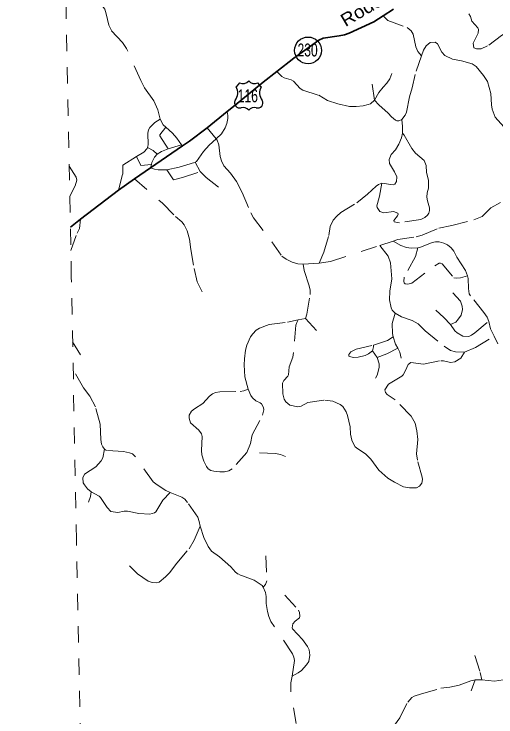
# Model space of a CAD drawing. Extents: x 220.8 to 246.7, y 7287.6 to 7315.8.
# Drawn here: x 220.754 to 223.739, y 7294.66 to 7299.009 of the extents above; entities that cross this region are included whole.
import ezdxf
from ezdxf.enums import TextEntityAlignment as Align

# ---------------------------------------------------------------- set-up
doc = ezdxf.new("R2010")
doc.units = 0
doc.header["$LTSCALE"] = 0.032
for name, pattern in [('DOTTED', [1.5, 0.3, -1.2]), ('MEDIUM_DASHED', [4.5, 3, -1.5]), ('SHORT_DASHED', [2.7, 1.5, -1.2])]:
    doc.linetypes.add(name, pattern=pattern)
for name, color, linetype, lineweight in [('12', 7, 'Continuous', 25), ('13', 7, 'Continuous', 25), ('2', 7, 'Continuous', 35), ('35', 7, 'SHORT_DASHED', 13), ('6', 7, 'MEDIUM_DASHED', 13), ('7', 7, 'DOTTED', 13)]:
    doc.layers.add(name, color=color, linetype=linetype, lineweight=lineweight)
doc.layers.add('61', color=7, linetype='Continuous')

msp = doc.modelspace()

# ---------------------------------------------------------------- linework, layer by layer
at = {"layer": '12'}
for p, q in [((222.1503, 7298.5835), (222.1294, 7298.5592)), ((222.2856, 7298.5594), (222.2646, 7298.5835))]:
    msp.add_line(p, q, dxfattribs=at)
for centre, radius, start, end in [((222.1711, 7298.6236), 0.0452, 242.5287, 323.4161), ((222.2437, 7298.6236), 0.0452, 216.5968, 297.4912), ((222.0662, 7298.521), 0.0738, 320.9608, 31.1419), ((222.3486, 7298.521), 0.0738, 148.687, 219.0536), ((222.1514, 7298.4594), 0.0316, 151.5003, 286.5066), ((222.2635, 7298.4594), 0.0316, 253.4942, 28.4996), ((222.1734, 7298.3877), 0.0433, 38.3472, 107.6219), ((222.2414, 7298.3877), 0.0433, 72.467, 141.6528)]:
    msp.add_arc(centre, radius, start, end, dxfattribs=at)
at = {"layer": '13'}
msp.add_circle((222.5751, 7298.7839), 0.083, dxfattribs=at)
at = {"layer": '2'}
msp.add_lwpolyline([(221.1029, 7297.6911), (221.1659, 7297.7392), (221.4019, 7297.9193), (221.5013, 7297.9903), (221.6003, 7298.0579), (221.7976, 7298.1926), (221.8414, 7298.2225), (221.95, 7298.3053), (222.0739, 7298.4051), (222.1143, 7298.4377), (222.298, 7298.5873), (222.3818, 7298.653), (222.4869, 7298.7356), (222.6418, 7298.8484), (222.6693, 7298.8602), (222.7677, 7298.8733), (222.8005, 7298.8799), (222.8307, 7298.8904), (222.9829, 7298.9612), (223.0409, 7298.998), (223.1049, 7299.0386)], dxfattribs=at)
at = {"layer": '35'}
msp.add_lwpolyline([(221.3035, 7287.6034), (221.271, 7289.2329), (221.2386, 7290.8624), (221.2062, 7292.4919), (221.1738, 7294.1214), (221.1414, 7295.7509), (221.109, 7297.3804), (221.0767, 7299.0099), (221.0443, 7300.6394), (221.0121, 7302.2689), (220.9798, 7303.8984), (220.9475, 7305.5279), (220.9153, 7307.1574), (220.883, 7308.7869), (220.8508, 7310.4164), (220.8187, 7312.0459), (220.7865, 7313.6754), (220.7543, 7315.3049)], dxfattribs=at)
at = {"layer": '6'}
for p, q in [((221.95, 7298.3053), (222.0063, 7298.2361)), ((221.7919, 7298.2006), (221.7093, 7298.1757)), ((221.7919, 7298.2006), (221.7976, 7298.1926)), ((221.9077, 7298.0339), (221.8767, 7298.093))]:
    msp.add_line(p, q, dxfattribs=at)
for points in [[(221.6588, 7298.3593), (221.6455, 7298.4161), (221.6203, 7298.4715), (221.562, 7298.5515), (221.5389, 7298.5971), (221.4513, 7298.7962), (221.426, 7298.8327), (221.358, 7298.9063), (221.3412, 7298.94), (221.3257, 7299.0101), (221.3159, 7299.0402), (221.2539, 7299.1225)], [(222.0063, 7298.2361), (222.0399, 7298.2688), (222.062, 7298.3042), (222.0724, 7298.3323), (222.079, 7298.3618), (222.079, 7298.381), (222.0739, 7298.4051)], [(221.58, 7298.1827), (221.5845, 7298.1988), (221.5838, 7298.2717), (221.5866, 7298.292), (221.595, 7298.3074), (221.6259, 7298.339), (221.6588, 7298.3593)], [(221.6588, 7298.3593), (221.6778, 7298.3243), (221.6935, 7298.3085)], [(221.6935, 7298.3085), (221.6567, 7298.2619), (221.6581, 7298.2549), (221.7093, 7298.1757)], [(221.6935, 7298.3085), (221.736, 7298.2724), (221.7633, 7298.2408), (221.7919, 7298.2006)], [(221.8767, 7298.093), (221.8841, 7298.0967), (221.9276, 7298.158), (221.9631, 7298.1986), (222.0063, 7298.2361)], [(222.0063, 7298.2361), (222.0126, 7298.2289), (222.0227, 7298.2006), (222.0318, 7298.1274), (222.0382, 7298.1009), (222.0537, 7298.0707), (222.094, 7298.025), (222.1314, 7297.9729), (222.168, 7297.9044), (222.221, 7297.7791), (222.2366, 7297.749), (222.3508, 7297.599), (222.413, 7297.5113), (222.4395, 7297.4921), (222.4761, 7297.4729), (222.5117, 7297.4628), (222.5453, 7297.4621), (222.6438, 7297.4675), (222.7138, 7297.4784), (223.0201, 7297.5772), (223.1024, 7297.6042)], [(221.5122, 7298.127), (221.5571, 7298.1553), (221.5782, 7298.1763), (221.58, 7298.1827)], [(221.58, 7298.1827), (221.6153, 7298.1644), (221.6416, 7298.1414)], [(221.6416, 7298.1414), (221.6231, 7298.123), (221.6076, 7298.0908), (221.6049, 7298.0787)], [(221.7093, 7298.1757), (221.6672, 7298.1581), (221.6416, 7298.1414)], [(221.4019, 7297.9193), (221.4274, 7298.0192), (221.4281, 7298.0739), (221.5122, 7298.127)], [(221.5122, 7298.127), (221.5389, 7298.0718), (221.6049, 7298.0787)], [(221.7015, 7298.0455), (221.7762, 7298.0613), (221.8767, 7298.093)], [(221.0954, 7298.0676), (221.1392, 7297.9996), (221.1427, 7297.9807), (221.1336, 7297.947), (221.0991, 7297.8825)], [(221.6049, 7298.0787), (221.6003, 7298.0579), (221.6234, 7298.0487), (221.647, 7298.045), (221.7015, 7298.0455)], [(221.7015, 7298.0455), (221.7423, 7297.9837), (221.7969, 7297.9977), (221.9077, 7298.0339)], [(221.9077, 7298.0339), (221.9431, 7297.997), (222.0207, 7297.9387)], [(223.1024, 7297.6042), (223.1306, 7297.6137), (223.2449, 7297.631), (223.2824, 7297.6411), (223.3848, 7297.6841), (223.4652, 7297.7005), (223.6024, 7297.7352), (223.6526, 7297.7563), (223.7066, 7297.8102), (223.7678, 7297.8431)], [(221.1057, 7297.5453), (221.1446, 7297.6527), (221.1603, 7297.6822), (221.1659, 7297.7392)], [(223.7503, 7296.9678), (223.7272, 7297.0158), (223.7047, 7297.0602), (223.6937, 7297.1074), (223.6834, 7297.134), (223.6647, 7297.1623), (223.5806, 7297.2658), (223.5737, 7297.2782), (223.5682, 7297.3106), (223.5668, 7297.3734), (223.5622, 7297.3891), (223.5495, 7297.4217), (223.4971, 7297.5045), (223.4785, 7297.541), (223.4606, 7297.5617), (223.4385, 7297.5803), (223.415, 7297.5921), (223.3867, 7297.599), (223.3647, 7297.599), (223.3433, 7297.5955), (223.2681, 7297.5645), (223.2552, 7297.5626), (223.2129, 7297.5603), (223.1846, 7297.5638), (223.1488, 7297.5762), (223.1024, 7297.6042)], [(222.3237, 7295.3115), (222.3155, 7295.3612), (222.3155, 7295.4042), (222.3114, 7295.4294), (222.2975, 7295.4626), (222.2909, 7295.4737), (222.2405, 7295.5057), (222.1423, 7295.5439), (222.1253, 7295.5548), (222.0967, 7295.5882), (222.0265, 7295.6496), (221.9774, 7295.685), (221.9556, 7295.7136), (221.929, 7295.7702), (221.9073, 7295.8395), (221.901, 7295.8697), (221.8915, 7295.8963), (221.8295, 7295.9863), (221.8111, 7296.0067), (221.7927, 7296.019), (221.722, 7296.0485), (221.6952, 7296.0613), (221.64, 7296.0953), (221.6154, 7296.1144), (221.5057, 7296.2685), (221.4873, 7296.2869), (221.4696, 7296.2944), (221.4321, 7296.3019), (221.3264, 7296.308), (221.3148, 7296.3162), (221.3039, 7296.3305), (221.2964, 7296.3476), (221.2923, 7296.3769), (221.2876, 7296.4716), (221.2583, 7296.5786), (221.2242, 7296.6454), (221.1853, 7296.6966), (221.1204, 7296.8097)], [(222.5022, 7294.6182), (222.4675, 7294.8152), (222.4688, 7294.8711), (222.4773, 7294.9129), (222.492, 7295.0095), (222.4879, 7295.0293), (222.4791, 7295.0511), (222.3455, 7295.2501), (222.3318, 7295.2815), (222.3237, 7295.3115)]]:
    msp.add_lwpolyline(points, dxfattribs=at)
at = {"layer": '7'}
for p, q in [((222.9864, 7298.4753), (222.9673, 7298.6085)), ((222.5136, 7297.1159), (222.5599, 7297.1246)), ((222.5599, 7297.1246), (222.6296, 7297.0471)), ((221.1169, 7296.9816), (221.1657, 7296.9012)), ((223.0031, 7296.8848), (222.9732, 7296.9251)), ((223.61, 7294.8891), (223.5844, 7294.8218)), ((223.61, 7294.8891), (223.6514, 7294.8899))]:
    msp.add_line(p, q, dxfattribs=at)
for points in [[(223.9969, 7298.9547), (223.9678, 7298.9474), (223.8873, 7298.9067), (223.7978, 7298.89), (223.7734, 7298.8767), (223.6873, 7298.8116), (223.6479, 7298.7928), (223.6183, 7298.7928), (223.6012, 7298.8009), (223.5982, 7298.8288), (223.6286, 7298.8904), (223.6303, 7298.9127), (223.6264, 7298.9243), (223.5892, 7298.9654), (223.581, 7298.9945), (223.5703, 7299.0104)], [(223.0409, 7298.998), (223.0698, 7298.9692), (223.1886, 7298.9255), (223.2136, 7298.9042), (223.2261, 7298.8848), (223.243, 7298.8054), (223.2555, 7298.7767), (223.2767, 7298.751)], [(223.2767, 7298.751), (223.2907, 7298.7864), (223.3065, 7298.8121), (223.3313, 7298.8332), (223.3615, 7298.8344), (223.376, 7298.8249), (223.4046, 7298.7731), (223.4228, 7298.7528), (223.4696, 7298.7309), (223.5259, 7298.7201), (223.5905, 7298.7002), (223.6158, 7298.6849), (223.6618, 7298.6286), (223.6854, 7298.5913), (223.7065, 7298.5164), (223.7102, 7298.4464), (223.7144, 7298.4203), (223.7342, 7298.371), (223.7873, 7298.3118), (223.8274, 7298.2563), (223.8386, 7298.2348)], [(223.2767, 7298.751), (223.2386, 7298.6354), (223.2205, 7298.5535), (223.2042, 7298.4978), (223.1848, 7298.4009), (223.1767, 7298.3834), (223.1555, 7298.3559)], [(222.3818, 7298.653), (222.4126, 7298.6226), (222.427, 7298.6148), (222.4699, 7298.6029), (222.4846, 7298.5945), (222.5261, 7298.5491), (222.5426, 7298.5375), (222.6414, 7298.5069), (222.6962, 7298.475), (222.7605, 7298.4525), (222.8322, 7298.4366), (222.8737, 7298.4363), (222.9173, 7298.4409), (222.9479, 7298.4493), (222.9619, 7298.4542), (222.9864, 7298.4753)], [(222.9864, 7298.4753), (223.0137, 7298.5235), (223.0398, 7298.5576), (223.0628, 7298.5806), (223.0821, 7298.6087), (223.094, 7298.6422)], [(223.1555, 7298.3559), (223.1367, 7298.349), (223.1254, 7298.349), (223.1173, 7298.3528), (223.0911, 7298.3728), (223.0717, 7298.3953), (223.0129, 7298.4466), (222.9864, 7298.4753)], [(223.1593, 7298.2723), (223.1598, 7298.3124), (223.1555, 7298.3559)], [(223.1593, 7298.2723), (223.1702, 7298.2593), (223.2187, 7298.1769), (223.2411, 7298.1488), (223.2932, 7298.1019), (223.3068, 7298.0722), (223.3094, 7298.0279), (223.3219, 7297.9804), (223.3203, 7297.9314), (223.3135, 7297.9028), (223.3115, 7297.8767), (223.3141, 7297.8538), (223.3271, 7297.8105), (223.3281, 7297.7933), (223.3229, 7297.7772), (223.3151, 7297.7652), (223.2979, 7297.7511), (223.2729, 7297.7381), (223.1405, 7297.7172), (223.1087, 7297.724), (223.1056, 7297.7323), (223.1296, 7297.7605), (223.1332, 7297.7714), (223.1311, 7297.7766), (223.1051, 7297.7871), (223.0436, 7297.7798), (223.0206, 7297.7876), (223.0039, 7297.8126), (223.0019, 7297.823), (223.0045, 7297.8366), (223.017, 7297.8814), (223.0326, 7297.9617)], [(223.0326, 7297.9617), (223.1014, 7297.9528), (223.1118, 7297.9565), (223.1238, 7297.9731), (223.1243, 7298.0008), (223.1103, 7298.0336), (223.08, 7298.0852), (223.0769, 7298.1092), (223.0894, 7298.1399), (223.116, 7298.1696), (223.1374, 7298.203), (223.1535, 7298.2421), (223.1593, 7298.2723)], [(221.5013, 7297.9903), (221.673, 7297.8378), (221.7544, 7297.7572), (221.7931, 7297.7241), (221.8073, 7297.7052), (221.8262, 7297.6684), (221.8418, 7297.6169), (221.8492, 7297.5529), (221.869, 7297.4338), (221.8874, 7297.3528), (221.9187, 7297.2902)], [(222.6438, 7297.4675), (222.6735, 7297.5358), (222.7037, 7297.638), (222.7126, 7297.6938), (222.7308, 7297.7329), (222.7532, 7297.7589), (222.7777, 7297.7808), (222.8763, 7297.8418), (222.9435, 7297.8939), (222.9961, 7297.9434), (223.0112, 7297.9544), (223.0326, 7297.9617)], [(223.0201, 7297.5772), (223.0703, 7297.5114), (223.0858, 7297.4691), (223.0935, 7297.3709), (223.0806, 7297.295), (223.0785, 7297.2407), (223.0904, 7297.1917), (223.0966, 7297.1777), (223.1139, 7297.1583)], [(223.2552, 7297.5626), (223.2414, 7297.5093), (223.1711, 7297.3812), (223.1686, 7297.3541), (223.1702, 7297.3465), (223.1773, 7297.3407), (223.1928, 7297.3382), (223.2183, 7297.3444), (223.3602, 7297.452), (223.3861, 7297.4666), (223.3962, 7297.4674), (223.4058, 7297.4632), (223.4786, 7297.3762), (223.4961, 7297.3741), (223.52, 7297.3771), (223.5622, 7297.3891)], [(222.5599, 7297.1246), (222.5682, 7297.1513), (222.5881, 7297.2728), (222.5873, 7297.2995), (222.5813, 7297.3273), (222.5501, 7297.4225), (222.5453, 7297.4621)], [(223.4725, 7297.284), (223.5189, 7297.2329), (223.5299, 7297.2021), (223.5309, 7297.1801), (223.5231, 7297.1456), (223.5001, 7297.1139), (223.49, 7297.1033), (223.4581, 7297.0877)], [(223.1139, 7297.1583), (223.0966, 7297.0935), (223.0976, 7297.032), (223.1023, 7297.0116)], [(223.1139, 7297.1583), (223.1534, 7297.1359), (223.2201, 7297.1121), (223.2578, 7297.0914), (223.3007, 7297.0481), (223.4174, 7296.954), (223.4582, 7296.9267), (223.4877, 7296.9184), (223.5449, 7296.9171)], [(223.3654, 7297.1764), (223.4164, 7297.1314), (223.4581, 7297.0877)], [(222.2035, 7296.6882), (222.1827, 7296.7636), (222.1789, 7296.8377), (222.1808, 7296.8753), (222.1879, 7296.9298), (222.1958, 7296.9599), (222.2192, 7297.0107), (222.2323, 7297.0313), (222.2541, 7297.0524), (222.2737, 7297.0663), (222.3335, 7297.0874), (222.4471, 7297.1032), (222.5136, 7297.1159)], [(222.5136, 7297.1159), (222.505, 7297.1008), (222.5002, 7297.0842), (222.4847, 7296.9155), (222.4799, 7296.8855), (222.459, 7296.8255), (222.4536, 7296.7768), (222.4504, 7296.7693), (222.4242, 7296.7409), (222.4172, 7296.7259), (222.4199, 7296.6595), (222.4279, 7296.6269), (222.4376, 7296.6103), (222.4622, 7296.5899), (222.5109, 7296.5787), (222.5329, 7296.5824), (222.5736, 7296.6044), (222.678, 7296.6205), (222.7278, 7296.6146), (222.7744, 7296.5937), (222.7899, 7296.5808), (222.8113, 7296.5466), (222.8194, 7296.5257), (222.836, 7296.4545), (222.8381, 7296.41), (222.8467, 7296.3725), (222.8579, 7296.3452), (222.8676, 7296.3318), (222.8831, 7296.3179), (222.9307, 7296.2874), (222.9629, 7296.2542), (223.0132, 7296.1867), (223.07, 7296.1369), (223.1112, 7296.1118), (223.1669, 7296.0845), (223.2038, 7296.0775), (223.2477, 7296.0764), (223.2649, 7296.0877), (223.2788, 7296.1059), (223.2836, 7296.1284), (223.282, 7296.1428), (223.252, 7296.2483), (223.2472, 7296.2874), (223.2552, 7296.3763), (223.2493, 7296.4304), (223.2376, 7296.4775), (223.2135, 7296.5209), (223.1139, 7296.6221), (223.0641, 7296.6558), (223.0539, 7296.667), (223.0496, 7296.6831), (223.0732, 7296.7179), (223.1556, 7296.7688), (223.1642, 7296.7768), (223.1792, 7296.8025), (223.1953, 7296.8405), (223.2113, 7296.8539), (223.29, 7296.8432), (223.3966, 7296.8641), (223.4137, 7296.8636), (223.4576, 7296.8534), (223.4844, 7296.8571), (223.5203, 7296.8796), (223.5449, 7296.9171)], [(223.4581, 7297.0877), (223.4844, 7297.0486), (223.4978, 7297.0367), (223.5341, 7297.0165), (223.5704, 7297.0146), (223.5869, 7297.0211), (223.6076, 7297.0358), (223.6937, 7297.1074)], [(222.9805, 7296.9599), (223.0667, 7296.9887), (223.1023, 7297.0116)], [(223.1023, 7297.0116), (223.1173, 7296.967), (223.1309, 7296.941)], [(223.5449, 7296.9171), (223.6124, 7296.9449), (223.7272, 7297.0158)], [(222.9732, 7296.9251), (222.9504, 7296.9055), (222.9292, 7296.8962), (222.8853, 7296.8859), (222.8569, 7296.8848), (222.8326, 7296.891), (222.8285, 7296.8931), (222.828, 7296.9034), (222.8409, 7296.9194), (222.8735, 7296.9349), (222.9805, 7296.9599)], [(222.9732, 7296.9251), (222.9809, 7296.9494), (222.9805, 7296.9599)], [(223.0031, 7296.8848), (223.0625, 7296.906), (223.1309, 7296.941)], [(223.1309, 7296.941), (223.1431, 7296.9163), (223.1524, 7296.8797)], [(222.9938, 7296.7552), (223.0031, 7296.7753), (223.0155, 7296.8223), (223.0155, 7296.8445), (223.0031, 7296.8848)], [(222.1951, 7296.2968), (222.1042, 7296.194), (222.0848, 7296.1826), (222.0585, 7296.1756), (222.029, 7296.176), (221.9917, 7296.1804), (221.9724, 7296.1852), (221.9561, 7296.194), (221.9456, 7296.2085), (221.9293, 7296.2415), (221.9179, 7296.2814), (221.9144, 7296.3082), (221.9192, 7296.3948), (221.9153, 7296.4106), (221.8986, 7296.4334), (221.8476, 7296.4786), (221.8389, 7296.5076), (221.8393, 7296.5265), (221.8529, 7296.5516), (221.8709, 7296.5665), (221.9241, 7296.5994), (221.9654, 7296.6442), (221.9842, 7296.6587), (222.0018, 7296.6671), (222.0282, 7296.671), (222.1542, 7296.6732), (222.1775, 7296.6767), (222.2035, 7296.6882)], [(222.1951, 7296.2968), (222.2188, 7296.3518), (222.2289, 7296.4063), (222.2932, 7296.5263), (222.3015, 7296.5609), (222.2996, 7296.5748), (222.2861, 7296.597), (222.2793, 7296.6034), (222.2515, 7296.6161), (222.2301, 7296.6338), (222.2199, 7296.6496), (222.2035, 7296.6882)], [(221.3148, 7296.3162), (221.3034, 7296.264), (221.2929, 7296.2446), (221.2598, 7296.2078), (221.1899, 7296.1626), (221.1799, 7296.1385), (221.1831, 7296.1085), (221.1899, 7296.0949), (221.2083, 7296.0702), (221.2327, 7296.0527)], [(222.4358, 7296.2716), (222.4042, 7296.2829), (222.3741, 7296.2889), (222.1951, 7296.2968)], [(221.2146, 7295.9882), (221.2288, 7296.024), (221.2327, 7296.0527)], [(221.2327, 7296.0527), (221.2813, 7296.0261), (221.2902, 7296.0182), (221.3317, 7295.9551), (221.3538, 7295.931), (221.3964, 7295.9252), (221.4373, 7295.9336), (221.4573, 7295.9336), (221.5261, 7295.9178), (221.5949, 7295.9136), (221.6244, 7295.922), (221.6322, 7295.9283), (221.6748, 7296.0019), (221.722, 7296.0485)], [(221.4683, 7295.5956), (221.5194, 7295.5442), (221.5855, 7295.5003), (221.61, 7295.4911), (221.6337, 7295.4893), (221.6531, 7295.4942), (221.6929, 7295.5266), (221.716, 7295.5505), (221.7622, 7295.6114), (221.8381, 7295.7), (221.8704, 7295.7537), (221.9073, 7295.8395)], [(222.3131, 7295.6563), (222.3204, 7295.5023), (222.3117, 7295.4795), (222.2975, 7295.4626)], [(222.4309, 7295.4126), (222.5169, 7295.3207), (222.5229, 7295.3065), (222.5245, 7295.2826), (222.5223, 7295.2739), (222.4951, 7295.2516), (222.4815, 7295.2363), (222.4777, 7295.2113), (222.4793, 7295.2053), (222.5397, 7295.139), (222.5713, 7295.0954), (222.5816, 7295.0753), (222.5865, 7295.0426), (222.5794, 7295.0035), (222.5664, 7294.9823), (222.5354, 7294.948), (222.5147, 7294.9327), (222.4773, 7294.9129)], [(223.6079, 7295.039), (223.6414, 7294.9348), (223.6514, 7294.8899)], [(223.6514, 7294.8899), (223.7288, 7294.88), (223.7831, 7294.8889), (223.7967, 7294.8954), (223.8257, 7294.9216), (223.864, 7294.9436), (223.8907, 7294.9544), (223.901, 7294.9553), (223.9234, 7294.9511), (223.966, 7294.931), (224.025, 7294.88), (224.0512, 7294.8725), (224.0919, 7294.8678), (224.1302, 7294.8716), (224.2449, 7294.9165), (224.2655, 7294.9216), (224.3066, 7294.9254), (224.3338, 7294.9245), (224.359, 7294.9207), (224.404, 7294.9034), (224.4751, 7294.8561), (224.5256, 7294.7977), (224.5424, 7294.7828)], [(222.7708, 7294.317), (222.8684, 7294.3429), (222.9114, 7294.3593), (222.9835, 7294.4079), (223.0654, 7294.5108), (223.0813, 7294.5586), (223.0948, 7294.5852), (223.1426, 7294.6536), (223.1922, 7294.7518), (223.2188, 7294.7803), (223.2319, 7294.7878), (223.2773, 7294.8033), (223.398, 7294.8374), (223.4528, 7294.8435), (223.5112, 7294.8557), (223.5838, 7294.8837), (223.61, 7294.8891)]]:
    msp.add_lwpolyline(points, dxfattribs=at)

# ---------------------------------------------------------------- texts
at = {"layer": '61', "width": 1.1}
msp.add_text('Rodovia', height=0.08, rotation=30.532, dxfattribs=at).set_placement((222.9927, 7299.0373), align=Align.CENTER)
at = {"layer": '61', "width": 0.7}
for s, p in [('230', (222.5723, 7298.7467)), ('116', (222.202, 7298.4633))]:
    msp.add_text(s, height=0.08, dxfattribs=at).set_placement(p, align=Align.CENTER)

doc.saveas('drawing.dxf')
